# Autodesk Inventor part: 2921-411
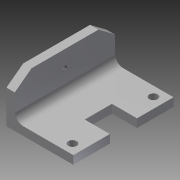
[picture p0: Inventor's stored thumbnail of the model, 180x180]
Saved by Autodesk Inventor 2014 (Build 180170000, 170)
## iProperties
Company: NHTSA/VRTC
Created: 2012-08
Part Number: 2921-411
Material: Steel, Mild
Document SubType Name: Modeling
Designer: Mike Vanvoorhis
Density: 7.86 g/cm^3
Mass: 2219.46 g
Surface Area: 527.567 cm^2
Volume: 282.375 cm^3
Project: CHILD SIDE IMPACT SLED
Description: BUMPER BASE
Stock Number: L5" x 3" x 1/2" x 0'-8" (203.2 mm)
Appearance: Steel
Author: Dave Walker
Title: Bumper Base
Subject: Child Side Impact Sled
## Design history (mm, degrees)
sketch "Sketch1"
  geometry: L1 (0, 0)-(101.6, 0); L2 (101.6, 0)-(101.6, 12.7); L3 (0, 0)-(0, 69.85); L4 (0, 69.85)-(12.7, 69.85); L5 (12.7, 69.85)-(12.7, 25.4); L6 (25.4, 12.7)-(101.6, 12.7); A1 r 12.7 centre (25.4, 25.4) between (12.7, 25.4) and (25.4, 12.7); 1 further point
  constraints: 12 end point, 3 perpendicular, 2 point on circle, 2 point on line, 2 tangent, 1 centre point, 1 horizontal, 1 parallel
  dimensions: "d0" = 101.6 distance of L1.start L1.end; "d1" = 12.7 distance of L1.end L2.end; "d2" = 69.85 distance of L1.start L3.end; "d3" = 12.7 distance of L3.end L4.end; "d5" = 57.15 distance of L4.end point (12.7, 12.7); "d6" = 12.7 radius of A1
extrude "Extrusion1" new body sketch "Sketch1" stored distance "d7" = 152.4; taper "d8" = 0 deg
chamfer "Chamfer1" distance "d9" = 25.4; stored, may be unused: second distance "d10" = 19.05, angle "d11" = 45 deg
chamfer "Chamfer2" distance "d12" = 19.05; stored, may be unused: second distance "d13" = 25.4, angle "d14" = 45 deg
sketch "Sketch2"
  geometry: L1 (-76.2, 0)-(-76.2, 152.4) reference; L2 (-76.2, 55.562)-(-38.1, 55.563); L3 (-76.2, 96.838)-(-38.1, 96.838); L4 (-38.1, 96.838)-(-38.1, 55.563); 1 further point
  constraints: 6 end point, 2 point on line, 1 parallel, 1 perpendicular
  dimensions: "d16" = 55.5625 distance of L1.start L2.start; "d18" = 55.5625 distance from line of L3 L1.end; "d55" = 38.1 distance between parallel lines of L1 L4
extrude "Extrusion2" cut sketch "Sketch2" distance "d19" = 12.7; taper "d20" = 0 deg
sketch "Sketch3"
  geometry: L1 (0, 0)-(-152.4, 0) reference; L2 (-76.2, 0)-(-76.2, 44.45); 2 further points; 1 other entity
  constraints: 2 end point, 1 midpoint, 1 vertical, 1 other
  dimensions: "d21" = 44.45 distance of L2.start L2.end
hole "Hole1" sketch "Sketch3" at (-76.2, 44.45) diameter "d22" = 6.4008; stored, may be unused: countersink angle "d26" = 82 deg, drill point angle "d28" = 118 deg; dims "d23" = 19.05, "d24" = 9.525, "d25" = 6.35, "d27" = 25.4
sketch "Sketch7"
  geometry: L1 (0, -152.4)-(0, 0) reference; 3 further points
  constraints: 1 vertical alignment
  dimensions: "d46" = 123 distance of point (-85.725, -137.7) point (-85.725, -14.7); "d54" = 85.725 distance from line of point (-85.725, -137.7) L1; "d56" = 61.5 vertical distance of point (-85.725, -14.7) point (0, -76.2) (= 0.5 x d46)
hole "Hole3" sketch "Sketch7" at (-85.725, -14.7), (-85.725, -137.7) diameter "d47" = 12.7; stored, may be unused: countersink angle "d51" = 82 deg, drill point angle "d53" = 118 deg; dims "d48" = 19.05, "d49" = 9.525, "d50" = 6.35, "d52" = 25.4
body "Solid1"
